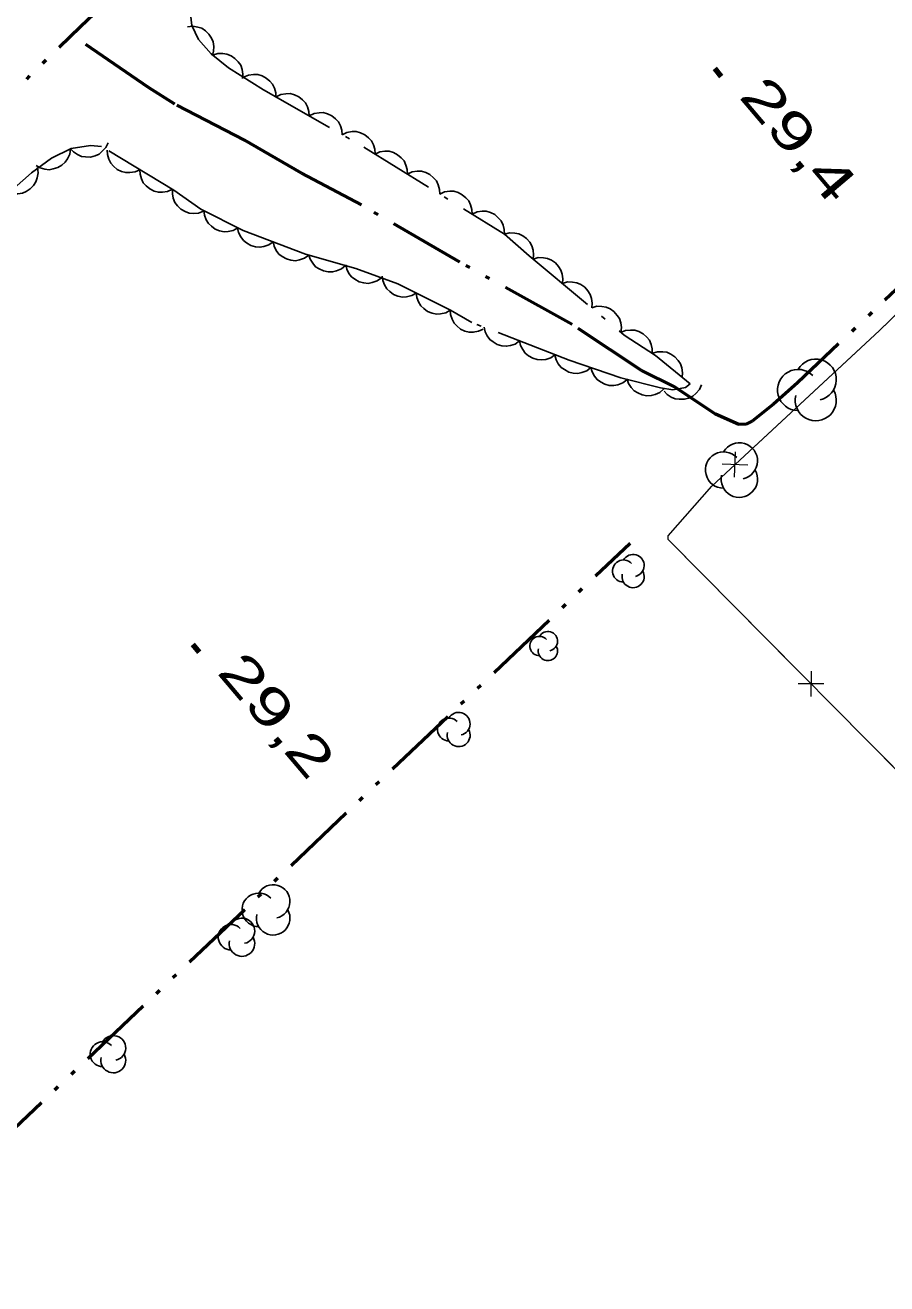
# Model space of a CAD drawing. Extents: x 386081 to 389416, y 5130568 to 5134082.
# Drawn here: x 388520.2 to 388588.2, y 5131762.8 to 5131862.1 of the extents above; entities that cross this region are included whole.
import ezdxf

# ---------------------------------------------------------------- set-up
doc = ezdxf.new("R2010")
doc.units = 0
doc.header["$LTSCALE"] = 1.2
doc.linetypes.add('DASH_DOUBLE_DOT', pattern=[9.2, 5, -1.2, 0.3, -1.2, 0.3, -1.2])
doc.linetypes.add('DOT_DASHED', pattern=[7.7, 5, -1.2, 0.3, -1.2])
for name, color, linetype, lineweight in [('3', 7, 'Continuous', 140), ('37', 7, 'Continuous', 13), ('4', 7, 'DASH_DOUBLE_DOT', 53), ('44', 7, 'Continuous', 25)]:
    doc.layers.add(name, color=color, linetype=linetype, lineweight=lineweight)

msp = doc.modelspace()

# ---------------------------------------------------------------- linework, layer by layer
at = {"layer": '3'}
for p, q in [((388574.61, 5131858.63), (388575.12, 5131858.02)), ((388533.46, 5131813.24), (388533.97, 5131812.63))]:
    msp.add_line(p, q, dxfattribs=at)
at = {"layer": '37'}
for p, q in [((388577.67, 5131828.77), (388585, 5131835.57)), ((388576.17, 5131826.41), (388576.24, 5131828.41)), ((388577.21, 5131827.37), (388575.2, 5131827.45)), ((388580.8, 5131811.55), (388573.76, 5131818.66)), ((388582.21, 5131811.13), (388582.2, 5131809.13)), ((388583.21, 5131810.13), (388581.2, 5131810.14)), ((388590.65, 5131801.6), (388583.61, 5131808.71))]:
    msp.add_line(p, q, dxfattribs=at)
for points in [[(388625.09, 5131795.45), (388610.23, 5131781.82), (388570.94, 5131821.51), (388570.95, 5131821.8), (388574.37, 5131825.71), (388587.61, 5131837.99), (388607.51, 5131857.3), (388628.3, 5131877.15), (388658.64, 5131905.79), (388671.61, 5131918.67)], [(388585, 5131835.57), (388587.61, 5131837.99), (388592.24, 5131842.48)], [(388573.76, 5131818.66), (388570.94, 5131821.51), (388570.95, 5131821.8), (388574.37, 5131825.71), (388574.74, 5131826.05)]]:
    msp.add_lwpolyline(points, dxfattribs=at)
at = {"layer": '4'}
for points in [[(388403.08, 5131676.15), (388398.8, 5131683.5), (388385.24, 5131705.68), (388376.19, 5131718.23), (388378.12, 5131720.75), (388380.58, 5131723.47), (388405.01, 5131746.47), (388448.58, 5131788.82), (388515.07, 5131852.58), (388524.6, 5131861.96), (388550.41, 5131886.49), (388583.66, 5131918.46), (388613.94, 5131948.36), (388649.63, 5131983.32), (388677.59, 5132010.13), (388707.98, 5132038.7), (388732.5, 5132062.17)], [(388606.25, 5131857.79), (388602.16, 5131853.97), (388592.39, 5131844.51), (388581.14, 5131833.87), (388579.24, 5131832.19), (388577.55, 5131830.84), (388577.09, 5131830.61), (388576.51, 5131830.57), (388574.66, 5131831.4), (388571.44, 5131833.55), (388568.85, 5131834.84), (388563.37, 5131838.46), (388554.51, 5131843.38), (388546.76, 5131847.88), (388542.04, 5131850.4), (388537.53, 5131852.98), (388532.04, 5131855.82), (388529.98, 5131857.13), (388523.94, 5131861.3)], [(388166.37, 5131434.07), (388187.89, 5131455.22), (388215.09, 5131482.63), (388233.63, 5131500.33), (388248.39, 5131515.01), (388284.53, 5131549.57), (388295.33, 5131560.48), (388304.99, 5131569.66), (388310.14, 5131575.04), (388349.08, 5131611.42), (388363.53, 5131625.78), (388381.6, 5131642.7), (388407.96, 5131667.76), (388412.46, 5131672.34), (388447.95, 5131706.57), (388473.53, 5131730.84), (388517.2, 5131773), (388567.95, 5131821.23)]]:
    msp.add_lwpolyline(points, dxfattribs=at)
at = {"layer": '44', "linetype": 'DOT_DASHED'}
msp.add_lwpolyline([(388533.2, 5131863.59), (388533.38, 5131862.04), (388533.92, 5131860.92), (388534.9, 5131859.79), (388536.29, 5131858.7), (388539.04, 5131856.97), (388546.94, 5131852.44), (388558.03, 5131845.59), (388559.97, 5131843.88), (388567.48, 5131837.63), (388569.93, 5131836.01), (388572.67, 5131833.79), (388572.31, 5131833.49), (388571.32, 5131833.32), (388570.33, 5131833.46), (388567.22, 5131834.26), (388563.13, 5131835.65), (388555.46, 5131838.62), (388553.78, 5131839.59), (388549.64, 5131841.66), (388546.32, 5131842.88), (388542.36, 5131844.01), (388537.44, 5131845.88), (388534.09, 5131847.54), (388531.98, 5131849.05), (388526.26, 5131852.48), (388525.39, 5131852.57), (388523.87, 5131852.33), (388522.32, 5131851.58), (388520.75, 5131850.42), (388517.47, 5131847.54)], dxfattribs=at)
at = {"layer": '44'}
for points in [[(388533.04, 5131861.93), (388533.46, 5131861.98), (388533.86, 5131861.91), (388534.17, 5131861.81), (388534.46, 5131861.61), (388534.73, 5131861.35), (388534.93, 5131861.03), (388535.07, 5131860.73), (388535.11, 5131860.38), (388535.1, 5131860.01), (388535.01, 5131859.66)], [(388535.03, 5131859.69), (388535.43, 5131859.82), (388535.83, 5131859.82), (388536.16, 5131859.78), (388536.49, 5131859.64), (388536.79, 5131859.44), (388537.05, 5131859.16), (388537.25, 5131858.9), (388537.36, 5131858.56), (388537.42, 5131858.2), (388537.39, 5131857.84)], [(388537.47, 5131857.95), (388537.86, 5131858.12), (388538.26, 5131858.17), (388538.59, 5131858.17), (388538.93, 5131858.06), (388539.25, 5131857.89), (388539.54, 5131857.64), (388539.76, 5131857.4), (388539.91, 5131857.08), (388540, 5131856.72), (388540.01, 5131856.36)], [(388540.04, 5131856.4), (388540.41, 5131856.58), (388540.81, 5131856.65), (388541.14, 5131856.66), (388541.48, 5131856.56), (388541.82, 5131856.41), (388542.12, 5131856.17), (388542.34, 5131855.93), (388542.5, 5131855.62), (388542.61, 5131855.26), (388542.64, 5131854.91)], [(388542.64, 5131854.91), (388543.02, 5131855.09), (388543.42, 5131855.15), (388543.75, 5131855.16), (388544.09, 5131855.07), (388544.42, 5131854.92), (388544.72, 5131854.67), (388544.95, 5131854.44), (388545.11, 5131854.13), (388545.22, 5131853.77), (388545.24, 5131853.41)], [(388545.24, 5131853.41), (388545.62, 5131853.6), (388546.02, 5131853.66), (388546.35, 5131853.67), (388546.69, 5131853.58), (388547.02, 5131853.42), (388547.32, 5131853.18), (388547.55, 5131852.95), (388547.71, 5131852.63), (388547.82, 5131852.28), (388547.85, 5131851.92)], [(388526.78, 5131852.79), (388526.6, 5131852.41), (388526.33, 5131852.11), (388526.08, 5131851.89), (388525.76, 5131851.75), (388525.4, 5131851.66), (388525.01, 5131851.67), (388524.69, 5131851.71), (388524.37, 5131851.85), (388524.06, 5131852.06), (388523.81, 5131852.32)], [(388523.82, 5131852.31), (388523.76, 5131851.89), (388523.59, 5131851.52), (388523.41, 5131851.25), (388523.14, 5131851.02), (388522.82, 5131850.83), (388522.46, 5131850.72), (388522.13, 5131850.66), (388521.79, 5131850.71), (388521.43, 5131850.82), (388521.12, 5131851)], [(388529.29, 5131850.66), (388528.91, 5131850.49), (388528.51, 5131850.43), (388528.18, 5131850.43), (388527.84, 5131850.53), (388527.51, 5131850.69), (388527.22, 5131850.94), (388526.99, 5131851.17), (388526.84, 5131851.49), (388526.74, 5131851.85), (388526.72, 5131852.21)], [(388547.83, 5131851.89), (388548.21, 5131852.06), (388548.61, 5131852.11), (388548.94, 5131852.11), (388549.28, 5131852.01), (388549.61, 5131851.84), (388549.9, 5131851.59), (388550.12, 5131851.35), (388550.27, 5131851.03), (388550.36, 5131850.67), (388550.38, 5131850.32)], [(388521.21, 5131850.83), (388521.27, 5131850.41), (388521.2, 5131850.01), (388521.1, 5131849.7), (388520.9, 5131849.41), (388520.65, 5131849.14), (388520.32, 5131848.94), (388520.03, 5131848.8), (388519.68, 5131848.75), (388519.31, 5131848.76), (388518.96, 5131848.85)], [(388531.86, 5131849.12), (388531.48, 5131848.95), (388531.08, 5131848.89), (388530.75, 5131848.89), (388530.41, 5131848.98), (388530.08, 5131849.15), (388529.79, 5131849.39), (388529.56, 5131849.63), (388529.41, 5131849.95), (388529.31, 5131850.3), (388529.29, 5131850.66)], [(388550.38, 5131850.32), (388550.76, 5131850.49), (388551.16, 5131850.54), (388551.49, 5131850.54), (388551.83, 5131850.43), (388552.16, 5131850.27), (388552.45, 5131850.01), (388552.67, 5131849.78), (388552.82, 5131849.46), (388552.92, 5131849.1), (388552.93, 5131848.74)], [(388534.31, 5131847.39), (388533.91, 5131847.24), (388533.51, 5131847.22), (388533.18, 5131847.24), (388532.85, 5131847.36), (388532.53, 5131847.55), (388532.26, 5131847.82), (388532.06, 5131848.08), (388531.93, 5131848.41), (388531.86, 5131848.77), (388531.87, 5131849.13)], [(388552.93, 5131848.74), (388553.31, 5131848.91), (388553.72, 5131848.96), (388554.05, 5131848.96), (388554.38, 5131848.86), (388554.71, 5131848.69), (388555, 5131848.44), (388555.22, 5131848.2), (388555.37, 5131847.88), (388555.47, 5131847.52), (388555.48, 5131847.16)], [(388537.02, 5131846.09), (388536.65, 5131845.88), (388536.26, 5131845.79), (388535.93, 5131845.77), (388535.58, 5131845.84), (388535.24, 5131845.97), (388534.93, 5131846.2), (388534.69, 5131846.41), (388534.51, 5131846.72), (388534.38, 5131847.07), (388534.33, 5131847.42)], [(388555.48, 5131847.16), (388555.87, 5131847.33), (388556.27, 5131847.39), (388556.6, 5131847.38), (388556.94, 5131847.28), (388557.27, 5131847.12), (388557.55, 5131846.86), (388557.77, 5131846.62), (388557.92, 5131846.3), (388558.02, 5131845.95), (388558.04, 5131845.59)], [(388539.8, 5131844.98), (388539.46, 5131844.74), (388539.07, 5131844.61), (388538.75, 5131844.55), (388538.4, 5131844.59), (388538.04, 5131844.69), (388537.71, 5131844.89), (388537.45, 5131845.08), (388537.25, 5131845.37), (388537.08, 5131845.7), (388537, 5131846.05)], [(388558.04, 5131845.58), (388558.44, 5131845.69), (388558.85, 5131845.67), (388559.17, 5131845.61), (388559.49, 5131845.46), (388559.78, 5131845.24), (388560.03, 5131844.94), (388560.2, 5131844.67), (388560.3, 5131844.33), (388560.33, 5131843.96), (388560.29, 5131843.6)], [(388542.61, 5131843.92), (388542.27, 5131843.68), (388541.88, 5131843.55), (388541.55, 5131843.49), (388541.2, 5131843.52), (388540.85, 5131843.63), (388540.52, 5131843.82), (388540.26, 5131844.01), (388540.05, 5131844.3), (388539.89, 5131844.63), (388539.8, 5131844.98)], [(388545.5, 5131843.11), (388545.18, 5131842.85), (388544.8, 5131842.69), (388544.49, 5131842.6), (388544.13, 5131842.61), (388543.77, 5131842.68), (388543.43, 5131842.84), (388543.15, 5131843.01), (388542.92, 5131843.28), (388542.73, 5131843.6), (388542.61, 5131843.94)], [(388560.29, 5131843.61), (388560.7, 5131843.73), (388561.1, 5131843.72), (388561.43, 5131843.67), (388561.75, 5131843.52), (388562.05, 5131843.31), (388562.3, 5131843.02), (388562.49, 5131842.75), (388562.59, 5131842.42), (388562.64, 5131842.05), (388562.6, 5131841.69)], [(388548.33, 5131842.14), (388548, 5131841.9), (388547.61, 5131841.76), (388547.29, 5131841.7), (388546.94, 5131841.73), (388546.58, 5131841.83), (388546.25, 5131842.02), (388545.98, 5131842.21), (388545.77, 5131842.49), (388545.61, 5131842.83), (388545.52, 5131843.17)], [(388551.08, 5131840.94), (388550.72, 5131840.74), (388550.32, 5131840.65), (388549.99, 5131840.62), (388549.64, 5131840.69), (388549.3, 5131840.83), (388548.99, 5131841.05), (388548.75, 5131841.27), (388548.57, 5131841.58), (388548.44, 5131841.93), (388548.4, 5131842.28)], [(388562.6, 5131841.69), (388563, 5131841.81), (388563.41, 5131841.8), (388563.74, 5131841.75), (388564.05, 5131841.61), (388564.36, 5131841.39), (388564.61, 5131841.1), (388564.79, 5131840.83), (388564.89, 5131840.5), (388564.94, 5131840.13), (388564.91, 5131839.77)], [(388553.76, 5131839.6), (388553.4, 5131839.39), (388553, 5131839.31), (388552.67, 5131839.28), (388552.33, 5131839.35), (388551.98, 5131839.49), (388551.67, 5131839.71), (388551.43, 5131839.93), (388551.26, 5131840.24), (388551.13, 5131840.58), (388551.08, 5131840.94)], [(388564.91, 5131839.77), (388565.31, 5131839.89), (388565.71, 5131839.88), (388566.04, 5131839.83), (388566.36, 5131839.69), (388566.66, 5131839.48), (388566.91, 5131839.18), (388567.1, 5131838.92), (388567.2, 5131838.58), (388567.25, 5131838.21), (388567.21, 5131837.85)], [(388556.36, 5131838.1), (388555.99, 5131837.92), (388555.58, 5131837.85), (388555.25, 5131837.85), (388554.91, 5131837.94), (388554.58, 5131838.09), (388554.28, 5131838.34), (388554.06, 5131838.57), (388553.9, 5131838.89), (388553.79, 5131839.24), (388553.76, 5131839.6)], [(388559.23, 5131837.16), (388558.88, 5131836.92), (388558.5, 5131836.8), (388558.17, 5131836.74), (388557.82, 5131836.78), (388557.47, 5131836.88), (388557.14, 5131837.08), (388556.88, 5131837.27), (388556.67, 5131837.56), (388556.51, 5131837.89), (388556.43, 5131838.24)], [(388567.19, 5131837.82), (388567.58, 5131837.98), (388567.98, 5131838.02), (388568.31, 5131838.01), (388568.64, 5131837.9), (388568.97, 5131837.72), (388569.25, 5131837.46), (388569.46, 5131837.21), (388569.6, 5131836.89), (388569.69, 5131836.53), (388569.69, 5131836.17)], [(388562.03, 5131836.08), (388561.68, 5131835.84), (388561.3, 5131835.71), (388560.97, 5131835.66), (388560.62, 5131835.7), (388560.27, 5131835.8), (388559.94, 5131835.99), (388559.68, 5131836.19), (388559.47, 5131836.48), (388559.31, 5131836.81), (388559.23, 5131837.16)], [(388564.85, 5131835.07), (388564.52, 5131834.81), (388564.13, 5131834.67), (388563.81, 5131834.6), (388563.46, 5131834.62), (388563.1, 5131834.71), (388562.77, 5131834.9), (388562.5, 5131835.08), (388562.28, 5131835.36), (388562.1, 5131835.68), (388562.01, 5131836.03)], [(388569.71, 5131836.19), (388570.11, 5131836.31), (388570.51, 5131836.31), (388570.84, 5131836.27), (388571.16, 5131836.12), (388571.47, 5131835.92), (388571.72, 5131835.63), (388571.91, 5131835.36), (388572.02, 5131835.03), (388572.07, 5131834.66), (388572.04, 5131834.3)], [(388567.69, 5131834.1), (388567.36, 5131833.85), (388566.97, 5131833.71), (388566.65, 5131833.64), (388566.3, 5131833.66), (388565.94, 5131833.75), (388565.61, 5131833.93), (388565.34, 5131834.11), (388565.12, 5131834.39), (388564.94, 5131834.72), (388564.85, 5131835.07)], [(388570.61, 5131833.39), (388570.29, 5131833.11), (388569.92, 5131832.94), (388569.61, 5131832.85), (388569.26, 5131832.84), (388568.89, 5131832.91), (388568.54, 5131833.06), (388568.26, 5131833.22), (388568.02, 5131833.49), (388567.82, 5131833.8), (388567.7, 5131834.14)], [(388573.57, 5131833.71), (388573.4, 5131833.33), (388573.13, 5131833.02), (388572.88, 5131832.8), (388572.56, 5131832.66), (388572.21, 5131832.56), (388571.82, 5131832.56), (388571.5, 5131832.6), (388571.18, 5131832.74), (388570.86, 5131832.94), (388570.62, 5131833.2)]]:
    msp.add_lwpolyline(points, dxfattribs=at)
for centre, radius, start, end in [((388582.577, 5131834.107), 1.62, 282.26917, 149.72626), ((388581.183, 5131833.297), 1.62, 44.11537, 269.80396), ((388582.577, 5131832.487), 1.62, 166.93686, 29.62122), ((388576.549, 5131827.7), 1.435, 282.26917, 149.72626), ((388575.315, 5131826.983), 1.435, 44.11537, 269.80396), ((388576.549, 5131826.265), 1.435, 166.93686, 29.62122), ((388567.424, 5131819.02), 0.874, 44.11537, 269.80396), ((388567.424, 5131819.02), 0.874, 44.11537, 269.80396), ((388568.175, 5131819.457), 0.874, 282.26917, 149.72626), ((388568.175, 5131819.457), 0.874, 282.26917, 149.72626), ((388568.175, 5131818.583), 0.874, 166.93686, 29.62122), ((388568.175, 5131818.583), 0.874, 166.93686, 29.62122), ((388560.802, 5131813.107), 0.763, 44.11537, 269.80396), ((388560.802, 5131813.107), 0.763, 44.11537, 269.80396), ((388561.459, 5131813.489), 0.763, 282.26917, 149.72626), ((388561.459, 5131813.489), 0.763, 282.26917, 149.72626), ((388561.459, 5131812.726), 0.763, 166.93686, 29.62122), ((388561.459, 5131812.726), 0.763, 166.93686, 29.62122), ((388554.426, 5131806.98), 0.9, 282.26917, 149.72626), ((388554.426, 5131806.98), 0.9, 282.26917, 149.72626), ((388553.652, 5131806.53), 0.9, 44.11537, 269.80396), ((388553.652, 5131806.53), 0.9, 44.11537, 269.80396), ((388554.426, 5131806.081), 0.9, 166.93686, 29.62122), ((388554.426, 5131806.081), 0.9, 166.93686, 29.62122), ((388539.803, 5131792.972), 1.323, 282.26917, 149.72626), ((388539.803, 5131792.972), 1.323, 282.26917, 149.72626), ((388538.665, 5131792.31), 1.323, 44.11537, 269.80396), ((388538.665, 5131792.31), 1.323, 44.11537, 269.80396), ((388539.803, 5131791.648), 1.323, 166.93686, 29.62122), ((388539.803, 5131791.648), 1.323, 166.93686, 29.62122), ((388536.476, 5131790.153), 1.004, 44.11537, 269.80396), ((388536.476, 5131790.153), 1.004, 44.11537, 269.80396), ((388537.339, 5131790.655), 1.004, 282.26917, 149.72626), ((388537.339, 5131790.655), 1.004, 282.26917, 149.72626), ((388537.339, 5131789.651), 1.004, 166.93686, 29.62122), ((388537.339, 5131789.651), 1.004, 166.93686, 29.62122), ((388527.199, 5131781.421), 0.978, 282.26917, 149.72626), ((388527.199, 5131781.421), 0.978, 282.26917, 149.72626), ((388526.357, 5131780.932), 0.978, 44.11537, 269.80396), ((388526.357, 5131780.932), 0.978, 44.11537, 269.80396), ((388527.199, 5131780.443), 0.978, 166.93686, 29.62122), ((388527.199, 5131780.443), 0.978, 166.93686, 29.62122)]:
    msp.add_arc(centre, radius, start, end, dxfattribs=at)

# ---------------------------------------------------------------- texts
at = {"layer": '3', "width": 1.45}
for s, p in [('29,4   ', (388576.44, 5131856.41)), ('29,2   ', (388535.29, 5131811.02))]:
    msp.add_text(s, height=3, rotation=310.294, dxfattribs=at).set_placement(p)

doc.saveas('drawing.dxf')
